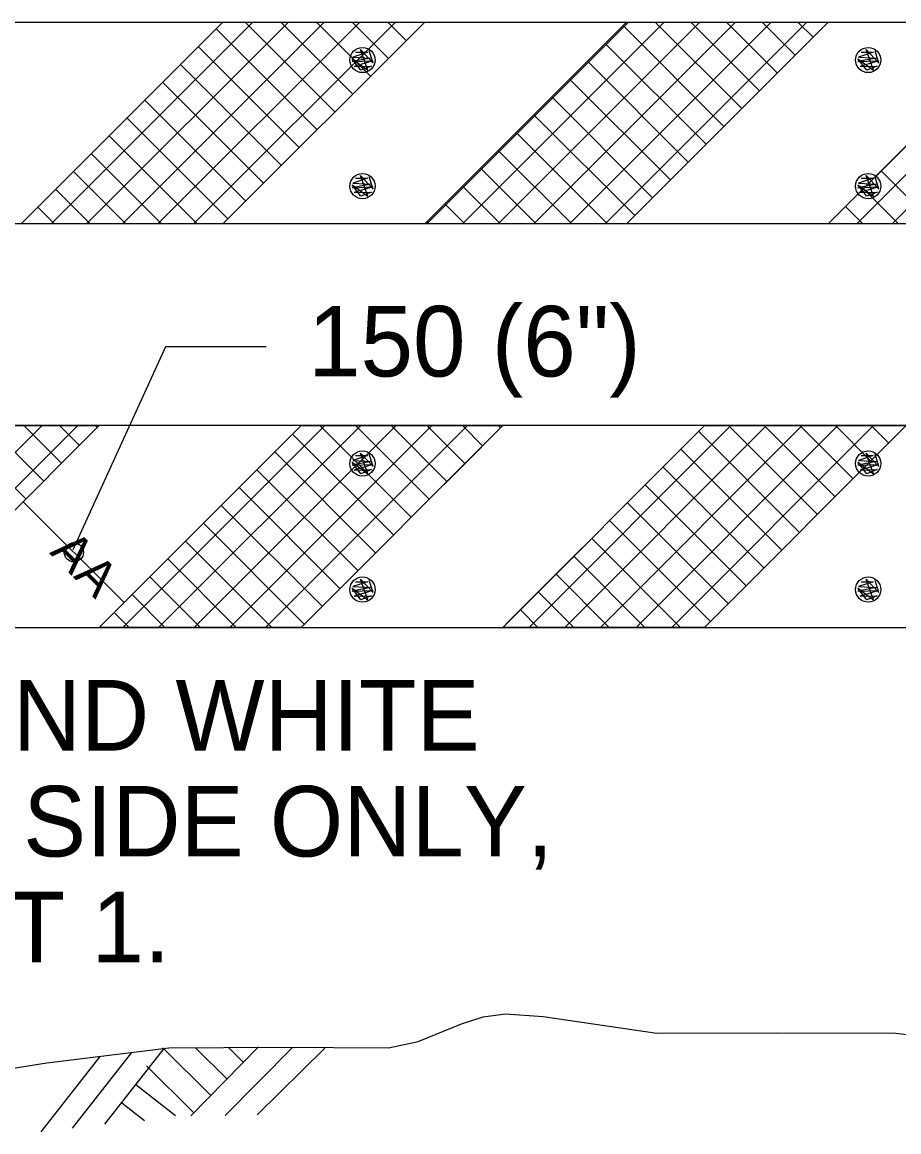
# Model space of a CAD drawing. Extents: x -4 to 901, y -468 to 720.
# Drawn here: x 178.8 to 220.5, y -332.2 to -279.4 of the extents above; entities that cross this region are included whole.
import ezdxf

# ---------------------------------------------------------------- set-up
doc = ezdxf.new("R2010")
doc.units = 0
doc.layers.add('2', color=7, linetype='Continuous')
doc.layers.add('3', color=7, linetype='Continuous')

msp = doc.modelspace()

# ---------------------------------------------------------------- linework, layer by layer
at = {"layer": '2'}
for p, q in [((110.77575, -279.407625), (242.46375, -279.407625)), ((178.72375, -289.007625), (188.32375, -279.407625)), ((188.32375, -289.007625), (197.92375, -279.407625)), ((197.92375, -289.007625), (207.52375, -279.407625)), ((207.52375, -289.007625), (217.12375, -279.407625)), ((217.12375, -289.007625), (226.72375, -279.407625)), ((195.19775, -280.835625), (194.50775, -281.069625)), ((194.63375, -280.835625), (195.19775, -280.835625)), ((195.20975, -281.693625), (194.86775, -280.709625)), ((194.86775, -280.709625), (195.46775, -281.351625)), ((195.46775, -281.351625), (195.28775, -280.769625)), ((219.26175, -280.835625), (218.57175, -281.069625)), ((218.69775, -280.835625), (219.26175, -280.835625)), ((219.27375, -281.693625), (218.93175, -280.709625)), ((218.93175, -280.709625), (219.53175, -281.351625)), ((219.53175, -281.351625), (219.35175, -280.769625)), ((195.35375, -281.117625), (194.46575, -281.285625)), ((194.89175, -281.693625), (194.46575, -281.147625)), ((194.46575, -281.147625), (195.20975, -281.693625)), ((194.46575, -281.285625), (195.45575, -281.249625)), ((194.50775, -281.069625), (195.35375, -281.117625)), ((195.45575, -281.249625), (194.57375, -281.519625)), ((194.96375, -281.207625), (194.96375, -281.207625)), ((194.96375, -281.207625), (194.96375, -281.207625)), ((219.41775, -281.117625), (218.52975, -281.285625)), ((218.95575, -281.693625), (218.52975, -281.147625)), ((218.52975, -281.147625), (219.27375, -281.693625)), ((218.52975, -281.285625), (219.51975, -281.249625)), ((218.57175, -281.069625), (219.41775, -281.117625)), ((219.51975, -281.249625), (218.63775, -281.519625)), ((219.02775, -281.207625), (219.02775, -281.207625)), ((219.02775, -281.207625), (219.02775, -281.207625)), ((194.57375, -281.519625), (195.38975, -281.501625)), ((195.38975, -281.501625), (194.89175, -281.693625)), ((218.63775, -281.519625), (219.45375, -281.501625)), ((219.45375, -281.501625), (218.95575, -281.693625)), ((195.20975, -287.693625), (194.86775, -286.709625)), ((194.86775, -286.709625), (195.46775, -287.351625)), ((219.27375, -287.693625), (218.93175, -286.709625)), ((218.93175, -286.709625), (219.53175, -287.351625)), ((195.35375, -287.117625), (194.46575, -287.285625)), ((194.89175, -287.693625), (194.46575, -287.147625)), ((194.46575, -287.147625), (195.20975, -287.693625)), ((194.46575, -287.285625), (195.45575, -287.249625)), ((195.19775, -286.835625), (194.50775, -287.069625)), ((194.50775, -287.069625), (195.35375, -287.117625)), ((195.45575, -287.249625), (194.57375, -287.519625)), ((194.63375, -286.835625), (195.19775, -286.835625)), ((194.96375, -287.207625), (194.96375, -287.207625)), ((194.96375, -287.207625), (194.96375, -287.207625)), ((195.46775, -287.351625), (195.28775, -286.769625)), ((219.41775, -287.117625), (218.52975, -287.285625)), ((218.95575, -287.693625), (218.52975, -287.147625)), ((218.52975, -287.147625), (219.27375, -287.693625)), ((218.52975, -287.285625), (219.51975, -287.249625)), ((219.26175, -286.835625), (218.57175, -287.069625)), ((218.57175, -287.069625), (219.41775, -287.117625)), ((219.51975, -287.249625), (218.63775, -287.519625)), ((218.69775, -286.835625), (219.26175, -286.835625)), ((219.02775, -287.207625), (219.02775, -287.207625)), ((219.02775, -287.207625), (219.02775, -287.207625)), ((219.53175, -287.351625), (219.35175, -286.769625)), ((194.57375, -287.519625), (195.38975, -287.501625)), ((195.38975, -287.501625), (194.89175, -287.693625)), ((218.63775, -287.519625), (219.45375, -287.501625)), ((219.45375, -287.501625), (218.95575, -287.693625)), ((242.2415, -289.007625), (110.77575, -289.007625)), ((242.2415, -298.607625), (110.77575, -298.607625)), ((172.83775, -308.207625), (182.43775, -298.607625)), ((182.43775, -308.207625), (192.03775, -298.607625)), ((192.03775, -308.207625), (201.63775, -298.607625)), ((201.63775, -308.207625), (211.23775, -298.607625)), ((211.23775, -308.207625), (220.83775, -298.607625)), ((195.20975, -300.893625), (194.86775, -299.909625)), ((194.86775, -299.909625), (195.46775, -300.551625)), ((200.61975, -299.627625), (196.99975, -303.245625)), ((219.27375, -300.893625), (218.93175, -299.909625)), ((218.93175, -299.909625), (219.53175, -300.551625)), ((195.35375, -300.317625), (194.46575, -300.485625)), ((194.89175, -300.893625), (194.46575, -300.347625)), ((194.46575, -300.347625), (195.20975, -300.893625)), ((194.46575, -300.485625), (195.45575, -300.449625)), ((195.19775, -300.035625), (194.50775, -300.269625)), ((194.50775, -300.269625), (195.35375, -300.317625)), ((195.45575, -300.449625), (194.57375, -300.719625)), ((194.63375, -300.035625), (195.19775, -300.035625)), ((194.96375, -300.407625), (194.96375, -300.407625)), ((194.96375, -300.407625), (194.96375, -300.407625)), ((195.46775, -300.551625), (195.28775, -299.969625)), ((219.41775, -300.317625), (218.52975, -300.485625)), ((218.95575, -300.893625), (218.52975, -300.347625)), ((218.52975, -300.347625), (219.27375, -300.893625)), ((218.52975, -300.485625), (219.51975, -300.449625)), ((219.26175, -300.035625), (218.57175, -300.269625)), ((218.57175, -300.269625), (219.41775, -300.317625)), ((219.51975, -300.449625), (218.63775, -300.719625)), ((218.69775, -300.035625), (219.26175, -300.035625)), ((219.02775, -300.407625), (219.02775, -300.407625)), ((219.02775, -300.407625), (219.02775, -300.407625)), ((219.53175, -300.551625), (219.35175, -299.969625)), ((194.57375, -300.719625), (195.38975, -300.701625)), ((195.38975, -300.701625), (194.89175, -300.893625)), ((218.63775, -300.719625), (219.45375, -300.701625)), ((219.45375, -300.701625), (218.95575, -300.893625)), ((183.61775, -307.027625), (178.81775, -302.227625)), ((205.41975, -304.427625), (201.79975, -308.045625)), ((195.19775, -306.035625), (194.50775, -306.269625)), ((194.50775, -306.269625), (195.35375, -306.317625)), ((194.63375, -306.035625), (195.19775, -306.035625)), ((195.20975, -306.893625), (194.86775, -305.909625)), ((194.86775, -305.909625), (195.46775, -306.551625)), ((195.46775, -306.551625), (195.28775, -305.969625)), ((219.26175, -306.035625), (218.57175, -306.269625)), ((218.57175, -306.269625), (219.41775, -306.317625)), ((218.69775, -306.035625), (219.26175, -306.035625)), ((219.27375, -306.893625), (218.93175, -305.909625)), ((218.93175, -305.909625), (219.53175, -306.551625)), ((219.53175, -306.551625), (219.35175, -305.969625)), ((195.35375, -306.317625), (194.46575, -306.485625)), ((194.89175, -306.893625), (194.46575, -306.347625)), ((194.46575, -306.347625), (195.20975, -306.893625)), ((194.46575, -306.485625), (195.45575, -306.449625)), ((195.45575, -306.449625), (194.57375, -306.719625)), ((194.57375, -306.719625), (195.38975, -306.701625)), ((195.38975, -306.701625), (194.89175, -306.893625)), ((194.96375, -306.407625), (194.96375, -306.407625)), ((194.96375, -306.407625), (194.96375, -306.407625)), ((219.41775, -306.317625), (218.52975, -306.485625)), ((218.95575, -306.893625), (218.52975, -306.347625)), ((218.52975, -306.347625), (219.27375, -306.893625)), ((218.52975, -306.485625), (219.51975, -306.449625)), ((219.51975, -306.449625), (218.63775, -306.719625)), ((218.63775, -306.719625), (219.45375, -306.701625)), ((219.45375, -306.701625), (218.95575, -306.893625)), ((219.02775, -306.407625), (219.02775, -306.407625)), ((219.02775, -306.407625), (219.02775, -306.407625)), ((110.77575, -308.207625), (242.2415, -308.207625)), ((181.16375, -332.033625), (183.98375, -328.437625)), ((182.70775, -331.845625), (185.52775, -328.249625)), ((185.45775, -328.223625), (187.75375, -330.489625)), ((186.79175, -331.447625), (190.01775, -328.175625)), ((187.01175, -328.213625), (188.50775, -329.689625)), ((188.43375, -331.435625), (191.60975, -328.217625)), ((188.58375, -328.203625), (189.29775, -328.907625)), ((189.94375, -331.411625), (193.16375, -328.235625)), ((179.67175, -332.213625), (182.47575, -328.637625)), ((184.68575, -329.075625), (186.92975, -331.289625)), ((184.18575, -329.961625), (186.07175, -331.439625)), ((183.50775, -330.827625), (184.58375, -331.671625))]:
    msp.add_line(p, q, dxfattribs=at)
for points in [[(180.14175, -289.007625), (189.73975, -279.409625)], [(181.83775, -289.007625), (191.43775, -279.407625)], [(183.53575, -289.007625), (193.13575, -279.407625)], [(185.23175, -289.007625), (194.83175, -279.407625)], [(186.92975, -289.007625), (196.52975, -279.407625)], [(192.80375, -284.529625), (188.00375, -279.729625)], [(193.65175, -283.679625), (189.37975, -279.407625)], [(194.49975, -282.831625), (191.07575, -279.407625)], [(195.34775, -281.983625), (192.77375, -279.407625)], [(196.19775, -281.135625), (194.46975, -279.407625)], [(197.04575, -280.285625), (196.16775, -279.407625)], [(197.89375, -279.437625), (197.86375, -279.407625)], [(198.01975, -289.007625), (207.61975, -279.409625)], [(199.71775, -289.007625), (209.31775, -279.407625)], [(201.41375, -289.007625), (211.01375, -279.407625)], [(203.11175, -289.007625), (212.71175, -279.407625)], [(204.80975, -289.007625), (214.40975, -279.407625)], [(206.50575, -289.007625), (216.10575, -279.407625)], [(212.16175, -284.371625), (207.36175, -279.571625)], [(213.00975, -283.521625), (208.89575, -279.407625)], [(213.85775, -282.673625), (210.59375, -279.407625)], [(214.70575, -281.825625), (212.28975, -279.407625)], [(215.55575, -280.977625), (213.98775, -279.407625)], [(216.40375, -280.127625), (215.68375, -279.407625)], [(218.47775, -289.007625), (228.07775, -279.407625)], [(220.17375, -289.007625), (229.77375, -279.407625)], [(191.95375, -285.377625), (187.15375, -280.577625)], [(211.31175, -285.219625), (206.51175, -280.419625)], [(191.10575, -286.225625), (186.30575, -281.425625)], [(210.46375, -286.067625), (205.66375, -281.267625)], [(190.25775, -287.075625), (185.45775, -282.275625)], [(209.61575, -286.915625), (204.81575, -282.115625)], [(208.76775, -287.765625), (203.96775, -282.965625)], [(189.40775, -287.923625), (184.60775, -283.123625)], [(188.55975, -288.771625), (183.75975, -283.971625)], [(207.91775, -288.613625), (203.11775, -283.813625)], [(187.09975, -289.007625), (182.91175, -284.819625)], [(206.61575, -289.007625), (202.26975, -284.661625)], [(185.40375, -289.007625), (182.06375, -285.669625)], [(204.91975, -289.007625), (201.42175, -285.509625)], [(183.70575, -289.007625), (181.21375, -286.517625)], [(203.22175, -289.007625), (200.57375, -286.359625)], [(222.16775, -289.007625), (219.64575, -286.485625)], [(201.52575, -289.007625), (199.72375, -287.207625)], [(182.00975, -289.007625), (180.36575, -287.365625)], [(220.47175, -289.007625), (218.79775, -287.333625)], [(180.31175, -289.007625), (179.51775, -288.213625)], [(199.82775, -289.007625), (198.87575, -288.055625)], [(218.77375, -289.007625), (217.94975, -288.183625)], [(198.13175, -289.007625), (198.02775, -288.905625)], [(190.38575, -294.861625), (185.58575, -294.861625), (181.17375, -304.525625)], [(170.11775, -308.207625), (179.71775, -298.607625)], [(171.81375, -308.207625), (181.41375, -298.607625)], [(178.94975, -302.097625), (175.46175, -298.607625)], [(179.79775, -301.247625), (177.15775, -298.607625)], [(180.64575, -300.399625), (178.85575, -298.607625)], [(181.49375, -299.551625), (180.55175, -298.607625)], [(182.34375, -298.703625), (182.24975, -298.607625)], [(183.56575, -308.207625), (193.16575, -298.607625)], [(185.26175, -308.207625), (194.86175, -298.609625)], [(186.95975, -308.207625), (196.55975, -298.607625)], [(188.65575, -308.207625), (198.25575, -298.607625)], [(190.35375, -308.207625), (199.95375, -298.607625)], [(197.28375, -302.961625), (192.93175, -298.607625)], [(198.13175, -302.113625), (194.62775, -298.607625)], [(198.98175, -301.263625), (196.32575, -298.607625)], [(199.82975, -300.415625), (198.02175, -298.607625)], [(200.67775, -299.567625), (199.71975, -298.607625)], [(201.52775, -298.719625), (201.41575, -298.607625)], [(202.88975, -308.207625), (212.48975, -298.607625)], [(204.58775, -308.207625), (214.18775, -298.607625)], [(206.28375, -308.207625), (215.88375, -298.607625)], [(207.98175, -308.207625), (217.58175, -298.607625)], [(209.67775, -308.207625), (219.27775, -298.607625)], [(216.60975, -302.835625), (212.38175, -298.607625)], [(217.45775, -301.987625), (214.07975, -298.607625)], [(218.30575, -301.139625), (215.77575, -298.607625)], [(219.15575, -300.291625), (217.47375, -298.607625)], [(220.00375, -299.441625), (219.16975, -298.607625)], [(196.43575, -303.809625), (191.63575, -299.009625)], [(215.76175, -303.685625), (210.96175, -298.885625)], [(195.58775, -304.659625), (190.78775, -299.859625)], [(214.91175, -304.533625), (210.11175, -299.733625)], [(194.73775, -305.507625), (189.93775, -300.707625)], [(214.06375, -305.381625), (209.26375, -300.581625)], [(213.21575, -306.229625), (208.41575, -301.429625)], [(193.88975, -306.355625), (189.08975, -301.555625)], [(193.04175, -307.203625), (188.24175, -302.403625)], [(212.36775, -307.079625), (207.56775, -302.279625)], [(192.19375, -308.053625), (187.39375, -303.253625)], [(211.51775, -307.927625), (206.71775, -303.127625)], [(190.65175, -308.207625), (186.54375, -304.101625)], [(210.10175, -308.207625), (205.86975, -303.975625)], [(188.95375, -308.207625), (185.69575, -304.949625)], [(208.40575, -308.207625), (205.02175, -304.823625)], [(206.70775, -308.207625), (204.17375, -305.673625)], [(187.25775, -308.207625), (184.84775, -305.797625)], [(185.55975, -308.207625), (183.99975, -306.647625)], [(205.01175, -308.207625), (203.32375, -306.521625)], [(183.86375, -308.207625), (183.14975, -307.495625)], [(203.31375, -308.207625), (202.47575, -307.369625)], [(174.14775, -329.847625), (179.93775, -328.927625), (185.75375, -328.221625), (190.97975, -328.187625), (196.19975, -328.221625), (197.60975, -327.911625), (199.67375, -327.075625), (200.71175, -326.735625), (201.76975, -326.597625), (203.56175, -326.731625), (208.96575, -327.525625), (214.65975, -327.503625), (220.34175, -327.525625), (221.85375, -327.711625)]]:
    msp.add_lwpolyline(points, dxfattribs=at)
for points in [[(197.92375, -289.007625), (207.52375, -279.407625), (217.12375, -279.407625), (207.52375, -289.007625)], [(217.12375, -289.007625), (226.72375, -279.407625), (236.32375, -279.407625), (226.72375, -289.007625)], [(163.23775, -308.207625), (172.83775, -298.607625), (182.43775, -298.607625), (172.83775, -308.207625)], [(182.43775, -308.207625), (192.03775, -298.607625), (201.63775, -298.607625), (192.03775, -308.207625)], [(201.63775, -308.207625), (211.23775, -298.607625), (220.83775, -298.607625), (211.23775, -308.207625)]]:
    msp.add_lwpolyline(points, close=True, dxfattribs=at)
for centre, radius in [((194.96405, -281.208528), 0.6), ((219.02693, -281.208528), 0.6), ((194.96405, -287.208528), 0.6), ((219.02693, -287.208528), 0.6), ((194.96405, -300.408528), 0.6), ((219.02693, -300.408528), 0.6), ((181.23101, -304.638768), 0.455664), ((194.96405, -306.408528), 0.6), ((219.02693, -306.408528), 0.6)]:
    msp.add_circle(centre, radius, dxfattribs=at)

# ---------------------------------------------------------------- texts
for p in [(180.03975, -304.671625), (181.17375, -305.805625)]:
    msp.add_text('A', height=1.727988, rotation=315.0037528, dxfattribs=at).set_placement(p)
at = {"layer": '3'}
for s, height, p in [('150 (6")', 3.36, (192.37075, -296.268125)), ('ALTERNATE RED AND WHITE', 3.359988, (136.87975, -314.071625)), ('STRIPES, TRAFFIC SIDE ONLY,', 3.359988, (136.87975, -319.111625)), ('SEE NOTE 1, SHEET 1.', 3.359988, (136.87975, -324.151625))]:
    msp.add_text(s, height=height, dxfattribs=at).set_placement(p)

doc.saveas('drawing.dxf')
